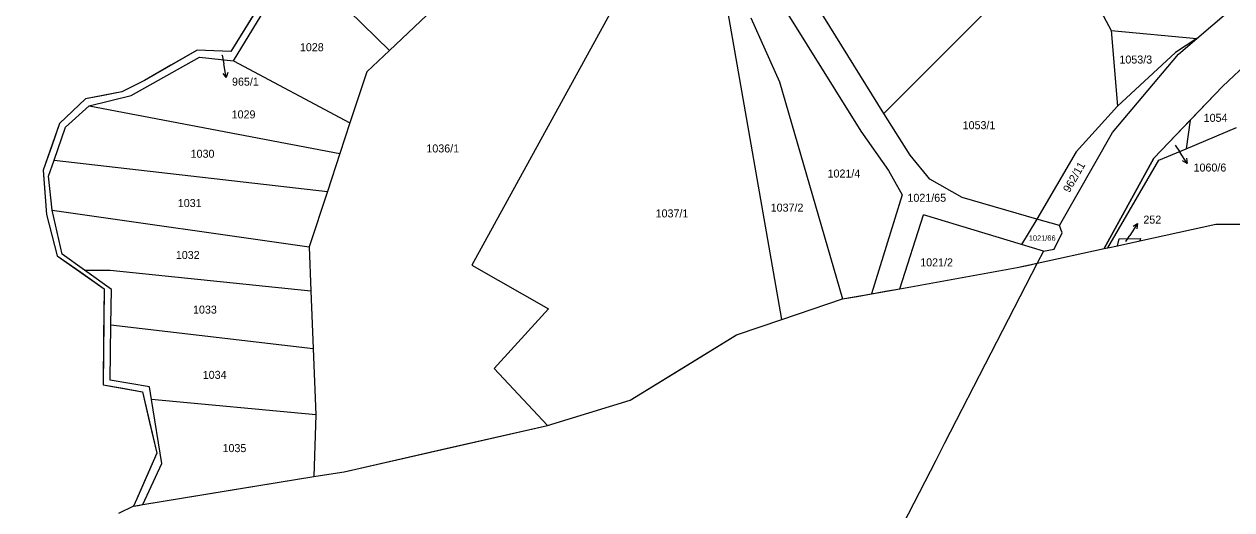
# Model space of a CAD drawing. Extents: x -593358 to -590116, y -1072518 to -1068420.
# Drawn here: x -592116.6 to -591859.9, y -1072346 to -1072242.9 of the extents above; entities that cross this region are included whole.
import ezdxf

# ---------------------------------------------------------------- set-up
doc = ezdxf.new("R2010")
doc.units = 0
for name, color, linetype in [('katastrální hranice', 7, 'Continuous'), ('Obvod s Dolní Čermnou', 7, 'Continuous'), ('Obvod s Petrovicemi', 7, 'Continuous'), ('Parcela KN', 7, 'Continuous'), ('Parcela ZE', 7, 'Continuous'), ('Parcelní číslo', 7, 'Continuous'), ('Parcelní číslo_stavební', 7, 'Continuous'), ('vnější obvod_šetřený', 7, 'Continuous'), ('Vrstva 16', 7, 'Continuous')]:
    doc.layers.add(name, color=color, linetype=linetype)

msp = doc.modelspace()

# ---------------------------------------------------------------- linework, layer by layer
at = {"layer": 'katastrální hranice'}
for p, q in [((-592055.36, -1072220.77), (-592072.66, -1072248.65)), ((-592079.82, -1072248.37), (-592091.01, -1072254.81)), ((-592072.66, -1072248.65), (-592079.82, -1072248.37)), ((-592091.01, -1072254.81), (-592095.8, -1072257.25)), ((-592103.54, -1072258.76), (-592109.04, -1072263.95)), ((-592095.8, -1072257.25), (-592103.54, -1072258.76)), ((-592109.04, -1072263.95), (-592112.5, -1072273.87)), ((-592112.5, -1072273.87), (-592111.82, -1072283.32)), ((-592111.82, -1072283.32), (-592109.54, -1072292.08)), ((-591863.38, -1072285.37), (-591808.69, -1072285.07)), ((-591879.47, -1072288.89), (-591863.38, -1072285.37)), ((-591887.09, -1072290.55), (-591886.26, -1072290.37)), ((-591886.26, -1072290.37), (-591884.27, -1072289.94)), ((-591884.27, -1072289.94), (-591879.47, -1072288.89)), ((-592109.54, -1072292.08), (-592099.56, -1072299.09)), ((-591901.33, -1072293.66), (-591887.09, -1072290.55)), ((-591930.52, -1072299.08), (-591905.57, -1072294.58)), ((-591905.57, -1072294.58), (-591901.33, -1072293.66)), ((-592099.56, -1072299.09), (-592099.77, -1072319.45)), ((-591942.66, -1072301.23), (-591936.49, -1072300.16)), ((-591936.49, -1072300.16), (-591930.52, -1072299.08)), ((-591955.53, -1072305.6), (-591942.66, -1072301.23)), ((-591965.19, -1072308.89), (-591955.53, -1072305.6)), ((-591987.79, -1072322.75), (-591965.19, -1072308.89)), ((-592099.77, -1072319.45), (-592091.42, -1072320.94)), ((-592091.42, -1072320.94), (-592088.36, -1072333.99)), ((-592005.33, -1072328.14), (-591987.79, -1072322.75)), ((-592048.58, -1072337.93), (-592005.33, -1072328.14)), ((-592088.36, -1072333.99), (-592092.65, -1072343.69)), ((-592091.35, -1072344.92), (-592055.03, -1072338.98)), ((-592055.03, -1072338.98), (-592048.58, -1072337.93)), ((-592092.65, -1072343.69), (-592093.34, -1072345.25)), ((-592093.34, -1072345.25), (-592091.35, -1072344.92))]:
    msp.add_line(p, q, dxfattribs=at)
at = {"layer": 'Obvod s Dolní Čermnou'}
msp.add_lwpolyline([(-591901.33, -1072293.66), (-591921, -1072331.9), (-591922.86, -1072335.52), (-591936.925, -1072362.86), (-591950.99, -1072390.2), (-591969.66, -1072408.07), (-591983.94, -1072415.24), (-592017.09, -1072428.37), (-592017.69, -1072431.21), (-592025.29, -1072429.74), (-592059.915, -1072446.61), (-592094.54, -1072463.48), (-592118.14, -1072474.19), (-592128.44, -1072476.41), (-592149.31, -1072484.55), (-592158.75, -1072481.42), (-592170.905, -1072457.595), (-592183.06, -1072433.77), (-592184.92, -1072430.22), (-592192.055, -1072416.605), (-592199.19, -1072402.99), (-592204.51, -1072392.83), (-592224.7, -1072353.79), (-592234.13, -1072342.7)], dxfattribs=at)
at = {"layer": 'Obvod s Petrovicemi'}
msp.add_line((-592093.34, -1072345.25), (-592096.54, -1072346.81), dxfattribs=at)
at = {"layer": 'Parcela KN'}
for p, q in [((-591955.53, -1072305.6), (-591969.8, -1072224.48)), ((-591933.86, -1072261.82), (-591896.2, -1072224.13)), ((-591896.2, -1072224.13), (-591885.59, -1072244.24)), ((-592072.08, -1072250.65), (-592058.85, -1072229.04)), ((-591867.4, -1072245.92), (-591851.52, -1072232.33)), ((-591989.37, -1072235.64), (-592021.41, -1072294.03)), ((-591933.86, -1072261.82), (-591950.15, -1072235.69)), ((-591955.72, -1072238.46), (-591938.81, -1072265.63)), ((-591962.14, -1072241.51), (-591956.04, -1072255.12)), ((-591885.59, -1072244.24), (-591867.4, -1072245.92)), ((-591867.4, -1072245.92), (-591871.89, -1072248.92)), ((-591871.28, -1072249.23), (-591867.4, -1072245.92)), ((-591885.29, -1072265.86), (-591871.28, -1072249.23)), ((-591871.89, -1072248.92), (-591884.25, -1072260.27)), ((-592093.79, -1072258.02), (-592079.31, -1072249.87)), ((-592079.31, -1072249.87), (-592072.08, -1072250.65)), ((-591855.97, -1072250.54), (-591861.84, -1072256.06)), ((-591956.04, -1072255.12), (-591942.66, -1072301.23)), ((-591861.84, -1072256.06), (-591868.78, -1072263.29)), ((-592102.76, -1072260.24), (-592093.79, -1072258.02)), ((-592107.75, -1072264.78), (-592102.76, -1072260.24)), ((-591928.33, -1072270.67), (-591933.86, -1072261.82)), ((-591884.25, -1072260.27), (-591893, -1072270)), ((-591868.78, -1072263.29), (-591876.49, -1072271.32)), ((-592110.19, -1072271.74), (-592107.75, -1072264.78)), ((-591938.81, -1072265.63), (-591932.87, -1072273.97)), ((-591896.54, -1072285.65), (-591885.29, -1072265.86)), ((-591869.62, -1072269.33), (-591858.95, -1072264.85)), ((-591875.46, -1072271.79), (-591869.62, -1072269.33)), ((-592111.38, -1072275.14), (-592110.19, -1072271.74)), ((-591924.12, -1072275.78), (-591928.33, -1072270.67)), ((-591893, -1072270), (-591901.4, -1072284.26)), ((-591876.49, -1072271.32), (-591887.09, -1072290.55)), ((-591886.26, -1072290.37), (-591875.46, -1072271.79)), ((-591932.87, -1072273.97), (-591929.99, -1072279.13)), ((-592110.59, -1072282.35), (-592111.38, -1072275.14)), ((-591917.28, -1072279.7), (-591924.12, -1072275.78)), ((-591929.99, -1072279.13), (-591936.49, -1072300.16)), ((-591901.4, -1072284.26), (-591917.28, -1072279.7)), ((-592108.51, -1072291.72), (-592110.59, -1072282.35)), ((-591930.52, -1072299.08), (-591925.45, -1072283.39)), ((-591904.62, -1072289.7), (-591925.45, -1072283.39)), ((-591896.54, -1072285.65), (-591901.4, -1072284.26)), ((-591897.67, -1072290.68), (-591896, -1072287.19)), ((-591896, -1072287.19), (-591896.54, -1072285.65)), ((-591899.99, -1072291.1), (-591904.62, -1072289.7)), ((-591884.27, -1072289.94), (-591883.87, -1072288.46)), ((-591883.87, -1072288.46), (-591879.34, -1072288.43)), ((-591879.34, -1072288.43), (-591879.47, -1072288.89)), ((-592103.72, -1072295.14), (-592108.51, -1072291.72)), ((-591899.99, -1072291.1), (-591901.33, -1072293.66)), ((-591899.99, -1072291.1), (-591897.67, -1072290.68)), ((-592097.98, -1072299.23), (-592103.72, -1072295.14)), ((-592021.41, -1072294.03), (-592005.12, -1072303.33)), ((-592098.11, -1072306.73), (-592097.98, -1072299.23)), ((-592005.12, -1072303.33), (-592016.67, -1072316.02)), ((-592098.31, -1072318.47), (-592098.11, -1072306.73)), ((-592016.67, -1072316.02), (-592005.33, -1072328.14)), ((-592089.91, -1072319.91), (-592098.31, -1072318.47)), ((-592089.48, -1072322.59), (-592089.91, -1072319.91)), ((-592087.29, -1072336.16), (-592089.48, -1072322.59)), ((-592091.35, -1072344.92), (-592087.29, -1072336.16))]:
    msp.add_line(p, q, dxfattribs=at)
at = {"layer": 'Parcela ZE'}
for p, q in [((-592058.85, -1072229.04), (-592038.94, -1072248.45)), ((-592022.45, -1072232.83), (-592038.94, -1072248.45)), ((-591885.59, -1072244.24), (-591884.25, -1072260.27)), ((-592038.94, -1072248.45), (-592043.77, -1072253.02)), ((-592072.08, -1072250.65), (-592047.33, -1072263.85)), ((-592043.77, -1072253.02), (-592047.33, -1072263.85)), ((-592102.76, -1072260.24), (-592049.47, -1072270.35)), ((-592047.33, -1072263.85), (-592049.47, -1072270.35)), ((-591868.78, -1072263.29), (-591869.62, -1072269.33)), ((-592110.19, -1072271.74), (-592052.12, -1072278.41)), ((-592049.47, -1072270.35), (-592052.12, -1072278.41)), ((-592052.12, -1072278.41), (-592056.01, -1072290.19)), ((-592110.59, -1072282.35), (-592056.01, -1072290.19)), ((-591901.4, -1072284.26), (-591904.62, -1072289.7)), ((-592056.01, -1072290.19), (-592055.63, -1072299.55)), ((-592103.72, -1072295.14), (-592098.26, -1072295.11)), ((-592098.26, -1072295.11), (-592055.63, -1072299.55)), ((-592055.63, -1072299.55), (-592055.15, -1072311.73)), ((-592098.11, -1072306.73), (-592055.15, -1072311.73)), ((-592055.15, -1072311.73), (-592054.59, -1072325.85)), ((-592054.59, -1072325.85), (-592089.48, -1072322.59)), ((-592054.59, -1072325.85), (-592055.03, -1072338.98))]:
    msp.add_line(p, q, dxfattribs=at)
at = {"layer": 'vnější obvod_šetřený'}
for p, q in [((-592064.01, -1072234.71), (-592072.66, -1072248.65)), ((-592079.82, -1072248.37), (-592085.415, -1072251.59)), ((-592076.24, -1072248.51), (-592079.82, -1072248.37)), ((-592072.66, -1072248.65), (-592076.24, -1072248.51)), ((-592085.415, -1072251.59), (-592091.01, -1072254.81)), ((-592093.405, -1072256.03), (-592095.8, -1072257.25)), ((-592091.01, -1072254.81), (-592093.405, -1072256.03)), ((-592103.54, -1072258.76), (-592106.29, -1072261.355)), ((-592099.67, -1072258.005), (-592103.54, -1072258.76)), ((-592095.8, -1072257.25), (-592099.67, -1072258.005)), ((-592106.29, -1072261.355), (-592109.04, -1072263.95)), ((-592109.04, -1072263.95), (-592110.77, -1072268.91)), ((-592110.77, -1072268.91), (-592112.5, -1072273.87)), ((-591887.09, -1072290.55), (-591876.49, -1072271.32)), ((-592112.5, -1072273.87), (-592112.16, -1072278.595)), ((-592112.16, -1072278.595), (-592111.82, -1072283.32)), ((-592111.82, -1072283.32), (-592110.68, -1072287.7)), ((-592110.68, -1072287.7), (-592109.54, -1072292.08)), ((-592109.54, -1072292.08), (-592104.55, -1072295.585)), ((-591901.33, -1072293.66), (-591887.09, -1072290.55)), ((-591918.045, -1072296.83), (-591905.57, -1072294.58)), ((-591905.57, -1072294.58), (-591903.45, -1072294.12)), ((-591903.45, -1072294.12), (-591901.33, -1072293.66)), ((-592104.55, -1072295.585), (-592099.56, -1072299.09)), ((-591930.52, -1072299.08), (-591918.045, -1072296.83)), ((-592099.56, -1072299.09), (-592099.665, -1072309.27)), ((-591939.575, -1072300.695), (-591936.49, -1072300.16)), ((-591936.49, -1072300.16), (-591933.505, -1072299.62)), ((-591933.505, -1072299.62), (-591930.52, -1072299.08)), ((-591949.095, -1072303.415), (-591942.66, -1072301.23)), ((-591942.66, -1072301.23), (-591939.575, -1072300.695)), ((-591960.36, -1072307.245), (-591955.53, -1072305.6)), ((-591955.53, -1072305.6), (-591949.095, -1072303.415)), ((-591965.19, -1072308.89), (-591960.36, -1072307.245)), ((-592099.665, -1072309.27), (-592099.77, -1072319.45)), ((-591976.49, -1072315.82), (-591965.19, -1072308.89)), ((-591987.79, -1072322.75), (-591976.49, -1072315.82)), ((-592099.77, -1072319.45), (-592095.595, -1072320.195)), ((-592095.595, -1072320.195), (-592091.42, -1072320.94)), ((-592091.42, -1072320.94), (-592089.89, -1072327.465)), ((-591996.56, -1072325.445), (-591987.79, -1072322.75)), ((-592005.33, -1072328.14), (-591996.56, -1072325.445)), ((-592089.89, -1072327.465), (-592088.36, -1072333.99)), ((-592026.955, -1072333.035), (-592005.33, -1072328.14)), ((-592088.36, -1072333.99), (-592090.505, -1072338.84)), ((-592048.58, -1072337.93), (-592026.955, -1072333.035)), ((-592090.505, -1072338.84), (-592092.65, -1072343.69)), ((-592073.19, -1072341.95), (-592055.03, -1072338.98)), ((-592055.03, -1072338.98), (-592051.805, -1072338.455)), ((-592051.805, -1072338.455), (-592048.58, -1072337.93)), ((-592092.65, -1072343.69), (-592092.995, -1072344.47)), ((-592091.35, -1072344.92), (-592073.19, -1072341.95)), ((-592092.995, -1072344.47), (-592093.34, -1072345.25)), ((-592093.34, -1072345.25), (-592092.345, -1072345.085)), ((-592092.345, -1072345.085), (-592091.35, -1072344.92))]:
    msp.add_line(p, q, dxfattribs=at)
msp.add_lwpolyline([(-591876.49, -1072271.32), (-591861.84, -1072256.06), (-591855.97, -1072250.54)], dxfattribs=at)
at = {"layer": 'Vrstva 16'}
for p, q in [((-592074.46, -1072249.48), (-592074.15, -1072251.28)), ((-592073.635, -1072254.236), (-592074.15, -1072251.28)), ((-591871.96, -1072268.57), (-591871.08, -1072269.95)), ((-591869.468, -1072272.48), (-591871.08, -1072269.95)), ((-591879.978, -1072285.236), (-591881.6, -1072287.76)), ((-591882.44, -1072289.07), (-591881.6, -1072287.76))]:
    msp.add_line(p, q, dxfattribs=at)
for points in [[(-592073.314, -1072253.165), (-592073.635, -1072254.236), (-592074.299, -1072253.336)], [(-591869.583, -1072271.368), (-591869.468, -1072272.48), (-591870.427, -1072271.905)], [(-591880.939, -1072285.807), (-591879.978, -1072285.236), (-591880.098, -1072286.348)]]:
    msp.add_lwpolyline(points, dxfattribs=at)

# ---------------------------------------------------------------- texts
at = {"layer": 'Parcelní číslo'}
for s, height, p in [('1028', 1.7, (-592057.966, -1072248.62)), ('965/1', 0.1, (-592074.644, -1072249.48)), ('1053/3', 1.7, (-591883.832, -1072251.24)), ('1029', 1.7, (-592072.466, -1072262.89)), ('1054', 1.7, (-591865.929, -1072263.62)), ('1053/1', 1.7, (-591917.147, -1072265.18)), ('1030', 1.7, (-592081.176, -1072271.25)), ('1036/1', 1.7, (-592031.09, -1072270.12)), ('1060/6', 0.1, (-591872.185, -1072268.57)), ('1021/4', 1.7, (-591945.847, -1072275.45)), ('1031', 1.7, (-592083.911, -1072281.72)), ('1021/65', 1.7, (-591928.873, -1072280.6)), ('1037/1', 1.7, (-591982.38, -1072283.92)), ('1037/2', 1.7, (-591957.932, -1072282.69)), ('1021/66', 1.14, (-591903.087, -1072288.88)), ('1032', 1.7, (-592084.333, -1072292.75)), ('1021/2', 1.7, (-591926.16, -1072294.32)), ('1033', 1.7, (-592080.676, -1072304.35)), ('1034', 1.7, (-592078.609, -1072318.21)), ('1035', 1.7, (-592074.406, -1072333.77))]:
    msp.add_text(s, height=height, dxfattribs=at).set_placement(p)
msp.add_text('962/11', height=1.7, rotation=60.21786, dxfattribs=at).set_placement((-591894.458, -1072278.788))
at = {"layer": 'Parcelní číslo_stavební'}
msp.add_text('252', height=0.1, dxfattribs=at).set_placement((-591882.566, -1072289.07))
at = {"layer": 'Vrstva 16'}
for s, p in [('965/1', (-592072.393, -1072255.94)), ('1060/6', (-591868.077, -1072274.18)), ('252', (-591878.743, -1072285.24))]:
    msp.add_text(s, height=1.7, dxfattribs=at).set_placement(p)

doc.saveas('drawing.dxf')
